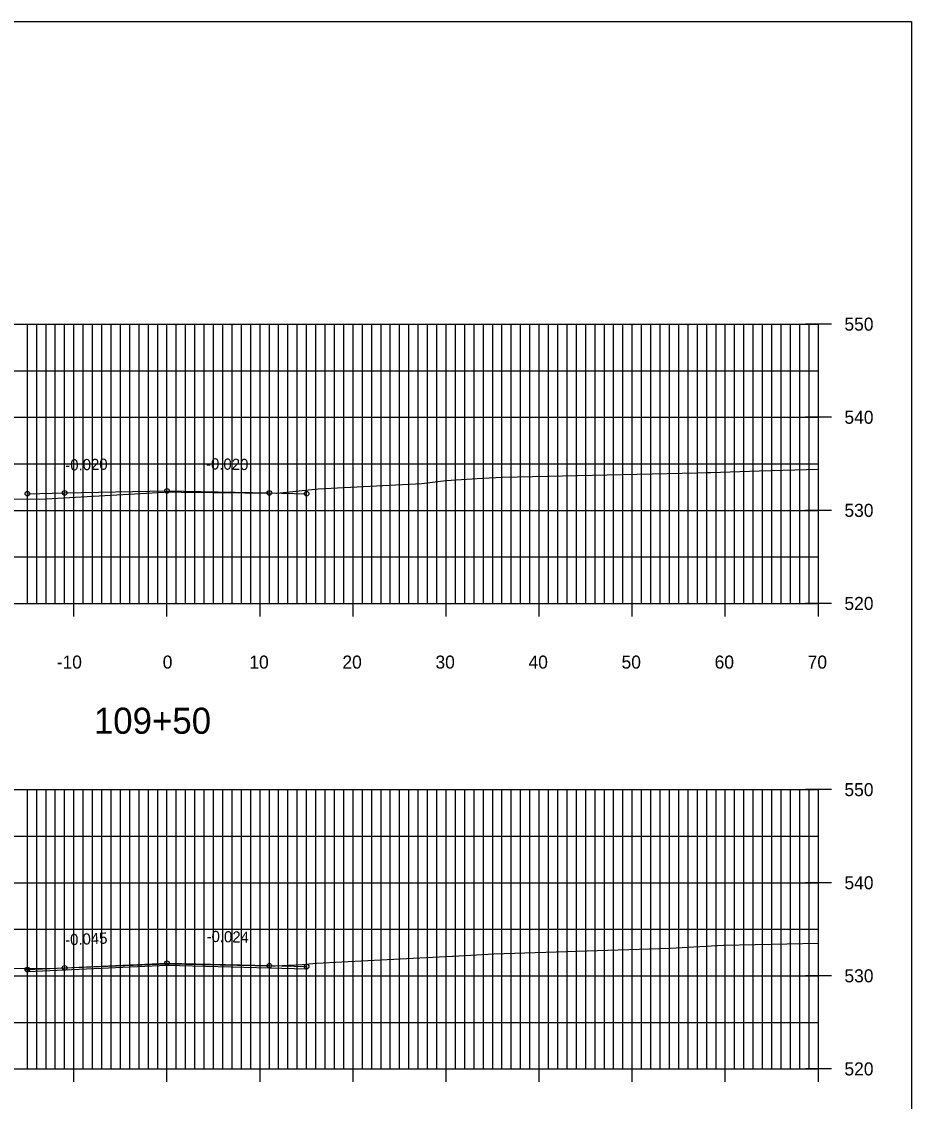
# Model space of a CAD drawing. Extents: x 1509063 to 1512863, y 401160 to 402918.
# Drawn here: x 1512407.1 to 1512502.7, y 402346.1 to 402462.1 of the extents above; entities that cross this region are included whole.
import ezdxf

# ---------------------------------------------------------------- set-up
doc = ezdxf.new("R2010")
doc.units = 0
for name, color, linetype in [('NBL1', 7, 'Continuous'), ('PET_P', 7, 'Continuous'), ('PRC', 7, 'Continuous'), ('PSP_P', 7, 'Continuous'), ('RBS_P', 7, 'Continuous'), ('XAX_P', 7, 'Continuous'), ('XAXTIC_P', 7, 'Continuous'), ('XAXTXT_P_T', 7, 'Continuous'), ('XGL_P', 7, 'Continuous'), ('XSL1_P', 7, 'Continuous'), ('XSL1_P_T', 7, 'Continuous'), ('XSL3_P', 7, 'Continuous'), ('XSLOG', 7, 'Continuous')]:
    doc.layers.add(name, color=color, linetype=linetype)

msp = doc.modelspace()

# ---------------------------------------------------------------- linework, layer by layer
at = {"layer": 'NBL1'}
msp.add_lwpolyline([(1512502.73, 402252.08), (1512182.73, 402252.08), (1512182.73, 402462.08), (1512502.73, 402462.08)], close=True, dxfattribs=at)
at = {"layer": 'PET_P'}
for centre in [(1512411.73, 402411.45), (1512433.73, 402411.45), (1512433.73, 402360.67), (1512411.73, 402360.43)]:
    msp.add_circle(centre, 0.25, dxfattribs=at)
at = {"layer": 'PRC'}
for centre in [(1512422.73, 402411.67), (1512422.73, 402360.93)]:
    msp.add_circle(centre, 0.25, dxfattribs=at)
at = {"layer": 'PSP_P'}
for centre in [(1512407.73, 402411.37), (1512437.73, 402411.37), (1512407.73, 402360.25), (1512437.73, 402360.57)]:
    msp.add_circle(centre, 0.25, dxfattribs=at)
at = {"layer": 'RBS_P'}
msp.add_lwpolyline([(1512407.73, 402360.25), (1512407.73, 402360.5), (1512407.73, 402360.25), (1512407.48, 402360.25), (1512407.73, 402360.25), (1512407.73, 402360), (1512407.73, 402360.25), (1512407.98, 402360.25)], dxfattribs=at)
at = {"layer": 'XAX_P'}
for p, q in [((1512422.73, 402399.58), (1512422.73, 402429.58)), ((1512492.73, 402399.58), (1512492.73, 402429.58)), ((1512352.73, 402399.58), (1512492.73, 402399.58)), ((1512422.73, 402349.58), (1512422.73, 402379.58)), ((1512492.73, 402349.58), (1512492.73, 402379.58)), ((1512352.73, 402349.58), (1512492.73, 402349.58))]:
    msp.add_line(p, q, dxfattribs=at)
at = {"layer": 'XAXTIC_P'}
for p, q in [((1512421.33, 402429.58), (1512424.13, 402429.58)), ((1512494.13, 402429.58), (1512491.33, 402429.58)), ((1512421.33, 402419.58), (1512424.13, 402419.58)), ((1512494.13, 402419.58), (1512491.33, 402419.58)), ((1512421.33, 402409.58), (1512424.13, 402409.58)), ((1512494.13, 402409.58), (1512491.33, 402409.58)), ((1512412.73, 402398.18), (1512412.73, 402400.98)), ((1512422.73, 402398.18), (1512422.73, 402400.98)), ((1512432.73, 402398.18), (1512432.73, 402400.98)), ((1512442.73, 402398.18), (1512442.73, 402400.98)), ((1512452.73, 402398.18), (1512452.73, 402400.98)), ((1512462.73, 402398.18), (1512462.73, 402400.98)), ((1512472.73, 402398.18), (1512472.73, 402400.98)), ((1512482.73, 402398.18), (1512482.73, 402400.98)), ((1512492.73, 402398.18), (1512492.73, 402400.98)), ((1512421.33, 402399.58), (1512424.13, 402399.58)), ((1512494.13, 402399.58), (1512491.33, 402399.58)), ((1512421.33, 402379.58), (1512424.13, 402379.58)), ((1512494.13, 402379.58), (1512491.33, 402379.58)), ((1512421.33, 402369.58), (1512424.13, 402369.58)), ((1512494.13, 402369.58), (1512491.33, 402369.58)), ((1512421.33, 402359.58), (1512424.13, 402359.58)), ((1512494.13, 402359.58), (1512491.33, 402359.58)), ((1512412.73, 402348.18), (1512412.73, 402350.98)), ((1512422.73, 402348.18), (1512422.73, 402350.98)), ((1512432.73, 402348.18), (1512432.73, 402350.98)), ((1512442.73, 402348.18), (1512442.73, 402350.98)), ((1512452.73, 402348.18), (1512452.73, 402350.98)), ((1512462.73, 402348.18), (1512462.73, 402350.98)), ((1512472.73, 402348.18), (1512472.73, 402350.98)), ((1512482.73, 402348.18), (1512482.73, 402350.98)), ((1512492.73, 402348.18), (1512492.73, 402350.98)), ((1512421.33, 402349.58), (1512424.13, 402349.58)), ((1512494.13, 402349.58), (1512491.33, 402349.58))]:
    msp.add_line(p, q, dxfattribs=at)
at = {"layer": 'XGL_P'}
for p, q in [((1512352.73, 402429.58), (1512492.73, 402429.58)), ((1512407.73, 402399.58), (1512407.73, 402429.58)), ((1512408.73, 402399.58), (1512408.73, 402429.58)), ((1512409.73, 402399.58), (1512409.73, 402429.58)), ((1512410.73, 402399.58), (1512410.73, 402429.58)), ((1512411.73, 402399.58), (1512411.73, 402429.58)), ((1512412.73, 402399.58), (1512412.73, 402429.58)), ((1512413.73, 402399.58), (1512413.73, 402429.58)), ((1512414.73, 402399.58), (1512414.73, 402429.58)), ((1512415.73, 402399.58), (1512415.73, 402429.58)), ((1512416.73, 402399.58), (1512416.73, 402429.58)), ((1512417.73, 402399.58), (1512417.73, 402429.58)), ((1512418.73, 402399.58), (1512418.73, 402429.58)), ((1512419.73, 402399.58), (1512419.73, 402429.58)), ((1512420.73, 402399.58), (1512420.73, 402429.58)), ((1512421.73, 402399.58), (1512421.73, 402429.58)), ((1512422.73, 402399.58), (1512422.73, 402429.58)), ((1512423.73, 402399.58), (1512423.73, 402429.58)), ((1512424.73, 402399.58), (1512424.73, 402429.58)), ((1512425.73, 402399.58), (1512425.73, 402429.58)), ((1512426.73, 402399.58), (1512426.73, 402429.58)), ((1512427.73, 402399.58), (1512427.73, 402429.58)), ((1512428.73, 402399.58), (1512428.73, 402429.58)), ((1512429.73, 402399.58), (1512429.73, 402429.58)), ((1512430.73, 402399.58), (1512430.73, 402429.58)), ((1512431.73, 402399.58), (1512431.73, 402429.58)), ((1512432.73, 402399.58), (1512432.73, 402429.58)), ((1512433.73, 402399.58), (1512433.73, 402429.58)), ((1512434.73, 402399.58), (1512434.73, 402429.58)), ((1512435.73, 402399.58), (1512435.73, 402429.58)), ((1512436.73, 402399.58), (1512436.73, 402429.58)), ((1512437.73, 402399.58), (1512437.73, 402429.58)), ((1512438.73, 402399.58), (1512438.73, 402429.58)), ((1512439.73, 402399.58), (1512439.73, 402429.58)), ((1512440.73, 402399.58), (1512440.73, 402429.58)), ((1512441.73, 402399.58), (1512441.73, 402429.58)), ((1512442.73, 402399.58), (1512442.73, 402429.58)), ((1512443.73, 402399.58), (1512443.73, 402429.58)), ((1512444.73, 402399.58), (1512444.73, 402429.58)), ((1512445.73, 402399.58), (1512445.73, 402429.58)), ((1512446.73, 402399.58), (1512446.73, 402429.58)), ((1512447.73, 402399.58), (1512447.73, 402429.58)), ((1512448.73, 402399.58), (1512448.73, 402429.58)), ((1512449.73, 402399.58), (1512449.73, 402429.58)), ((1512450.73, 402399.58), (1512450.73, 402429.58)), ((1512451.73, 402399.58), (1512451.73, 402429.58)), ((1512452.73, 402399.58), (1512452.73, 402429.58)), ((1512453.73, 402399.58), (1512453.73, 402429.58)), ((1512454.73, 402399.58), (1512454.73, 402429.58)), ((1512455.73, 402399.58), (1512455.73, 402429.58)), ((1512456.73, 402399.58), (1512456.73, 402429.58)), ((1512457.73, 402399.58), (1512457.73, 402429.58)), ((1512458.73, 402399.58), (1512458.73, 402429.58)), ((1512459.73, 402399.58), (1512459.73, 402429.58)), ((1512460.73, 402399.58), (1512460.73, 402429.58)), ((1512461.73, 402399.58), (1512461.73, 402429.58)), ((1512462.73, 402399.58), (1512462.73, 402429.58)), ((1512463.73, 402399.58), (1512463.73, 402429.58)), ((1512464.73, 402399.58), (1512464.73, 402429.58)), ((1512465.73, 402399.58), (1512465.73, 402429.58)), ((1512466.73, 402399.58), (1512466.73, 402429.58)), ((1512467.73, 402399.58), (1512467.73, 402429.58)), ((1512468.73, 402399.58), (1512468.73, 402429.58)), ((1512469.73, 402399.58), (1512469.73, 402429.58)), ((1512470.73, 402399.58), (1512470.73, 402429.58)), ((1512471.73, 402399.58), (1512471.73, 402429.58)), ((1512472.73, 402399.58), (1512472.73, 402429.58)), ((1512473.73, 402399.58), (1512473.73, 402429.58)), ((1512474.73, 402399.58), (1512474.73, 402429.58)), ((1512475.73, 402399.58), (1512475.73, 402429.58)), ((1512476.73, 402399.58), (1512476.73, 402429.58)), ((1512477.73, 402399.58), (1512477.73, 402429.58)), ((1512478.73, 402399.58), (1512478.73, 402429.58)), ((1512479.73, 402399.58), (1512479.73, 402429.58)), ((1512480.73, 402399.58), (1512480.73, 402429.58)), ((1512481.73, 402399.58), (1512481.73, 402429.58)), ((1512482.73, 402399.58), (1512482.73, 402429.58)), ((1512483.73, 402399.58), (1512483.73, 402429.58)), ((1512484.73, 402399.58), (1512484.73, 402429.58)), ((1512485.73, 402399.58), (1512485.73, 402429.58)), ((1512486.73, 402399.58), (1512486.73, 402429.58)), ((1512487.73, 402399.58), (1512487.73, 402429.58)), ((1512488.73, 402399.58), (1512488.73, 402429.58)), ((1512489.73, 402399.58), (1512489.73, 402429.58)), ((1512490.73, 402399.58), (1512490.73, 402429.58)), ((1512491.73, 402399.58), (1512491.73, 402429.58)), ((1512492.73, 402399.58), (1512492.73, 402429.58)), ((1512352.73, 402424.58), (1512492.73, 402424.58)), ((1512352.73, 402419.58), (1512492.73, 402419.58)), ((1512352.73, 402414.58), (1512492.73, 402414.58)), ((1512352.73, 402409.58), (1512492.73, 402409.58)), ((1512352.73, 402404.58), (1512492.73, 402404.58)), ((1512352.73, 402399.58), (1512492.73, 402399.58)), ((1512352.73, 402379.58), (1512492.73, 402379.58)), ((1512407.73, 402349.58), (1512407.73, 402379.58)), ((1512408.73, 402349.58), (1512408.73, 402379.58)), ((1512409.73, 402349.58), (1512409.73, 402379.58)), ((1512410.73, 402349.58), (1512410.73, 402379.58)), ((1512411.73, 402349.58), (1512411.73, 402379.58)), ((1512412.73, 402349.58), (1512412.73, 402379.58)), ((1512413.73, 402349.58), (1512413.73, 402379.58)), ((1512414.73, 402349.58), (1512414.73, 402379.58)), ((1512415.73, 402349.58), (1512415.73, 402379.58)), ((1512416.73, 402349.58), (1512416.73, 402379.58)), ((1512417.73, 402349.58), (1512417.73, 402379.58)), ((1512418.73, 402349.58), (1512418.73, 402379.58)), ((1512419.73, 402349.58), (1512419.73, 402379.58)), ((1512420.73, 402349.58), (1512420.73, 402379.58)), ((1512421.73, 402349.58), (1512421.73, 402379.58)), ((1512422.73, 402349.58), (1512422.73, 402379.58)), ((1512423.73, 402349.58), (1512423.73, 402379.58)), ((1512424.73, 402349.58), (1512424.73, 402379.58)), ((1512425.73, 402349.58), (1512425.73, 402379.58)), ((1512426.73, 402349.58), (1512426.73, 402379.58)), ((1512427.73, 402349.58), (1512427.73, 402379.58)), ((1512428.73, 402349.58), (1512428.73, 402379.58)), ((1512429.73, 402349.58), (1512429.73, 402379.58)), ((1512430.73, 402349.58), (1512430.73, 402379.58)), ((1512431.73, 402349.58), (1512431.73, 402379.58)), ((1512432.73, 402349.58), (1512432.73, 402379.58)), ((1512433.73, 402349.58), (1512433.73, 402379.58)), ((1512434.73, 402349.58), (1512434.73, 402379.58)), ((1512435.73, 402349.58), (1512435.73, 402379.58)), ((1512436.73, 402349.58), (1512436.73, 402379.58)), ((1512437.73, 402349.58), (1512437.73, 402379.58)), ((1512438.73, 402349.58), (1512438.73, 402379.58)), ((1512439.73, 402349.58), (1512439.73, 402379.58)), ((1512440.73, 402349.58), (1512440.73, 402379.58)), ((1512441.73, 402349.58), (1512441.73, 402379.58)), ((1512442.73, 402349.58), (1512442.73, 402379.58)), ((1512443.73, 402349.58), (1512443.73, 402379.58)), ((1512444.73, 402349.58), (1512444.73, 402379.58)), ((1512445.73, 402349.58), (1512445.73, 402379.58)), ((1512446.73, 402349.58), (1512446.73, 402379.58)), ((1512447.73, 402349.58), (1512447.73, 402379.58)), ((1512448.73, 402349.58), (1512448.73, 402379.58)), ((1512449.73, 402349.58), (1512449.73, 402379.58)), ((1512450.73, 402349.58), (1512450.73, 402379.58)), ((1512451.73, 402349.58), (1512451.73, 402379.58)), ((1512452.73, 402349.58), (1512452.73, 402379.58)), ((1512453.73, 402349.58), (1512453.73, 402379.58)), ((1512454.73, 402349.58), (1512454.73, 402379.58)), ((1512455.73, 402349.58), (1512455.73, 402379.58)), ((1512456.73, 402349.58), (1512456.73, 402379.58)), ((1512457.73, 402349.58), (1512457.73, 402379.58)), ((1512458.73, 402349.58), (1512458.73, 402379.58)), ((1512459.73, 402349.58), (1512459.73, 402379.58)), ((1512460.73, 402349.58), (1512460.73, 402379.58)), ((1512461.73, 402349.58), (1512461.73, 402379.58)), ((1512462.73, 402349.58), (1512462.73, 402379.58)), ((1512463.73, 402349.58), (1512463.73, 402379.58)), ((1512464.73, 402349.58), (1512464.73, 402379.58)), ((1512465.73, 402349.58), (1512465.73, 402379.58)), ((1512466.73, 402349.58), (1512466.73, 402379.58)), ((1512467.73, 402349.58), (1512467.73, 402379.58)), ((1512468.73, 402349.58), (1512468.73, 402379.58)), ((1512469.73, 402349.58), (1512469.73, 402379.58)), ((1512470.73, 402349.58), (1512470.73, 402379.58)), ((1512471.73, 402349.58), (1512471.73, 402379.58)), ((1512472.73, 402349.58), (1512472.73, 402379.58)), ((1512473.73, 402349.58), (1512473.73, 402379.58)), ((1512474.73, 402349.58), (1512474.73, 402379.58)), ((1512475.73, 402349.58), (1512475.73, 402379.58)), ((1512476.73, 402349.58), (1512476.73, 402379.58)), ((1512477.73, 402349.58), (1512477.73, 402379.58)), ((1512478.73, 402349.58), (1512478.73, 402379.58)), ((1512479.73, 402349.58), (1512479.73, 402379.58)), ((1512480.73, 402349.58), (1512480.73, 402379.58)), ((1512481.73, 402349.58), (1512481.73, 402379.58)), ((1512482.73, 402349.58), (1512482.73, 402379.58)), ((1512483.73, 402349.58), (1512483.73, 402379.58)), ((1512484.73, 402349.58), (1512484.73, 402379.58)), ((1512485.73, 402349.58), (1512485.73, 402379.58)), ((1512486.73, 402349.58), (1512486.73, 402379.58)), ((1512487.73, 402349.58), (1512487.73, 402379.58)), ((1512488.73, 402349.58), (1512488.73, 402379.58)), ((1512489.73, 402349.58), (1512489.73, 402379.58)), ((1512490.73, 402349.58), (1512490.73, 402379.58)), ((1512491.73, 402349.58), (1512491.73, 402379.58)), ((1512492.73, 402349.58), (1512492.73, 402379.58)), ((1512352.73, 402374.58), (1512492.73, 402374.58)), ((1512352.73, 402369.58), (1512492.73, 402369.58)), ((1512352.73, 402364.58), (1512492.73, 402364.58)), ((1512352.73, 402359.58), (1512492.73, 402359.58)), ((1512352.73, 402354.58), (1512492.73, 402354.58)), ((1512352.73, 402349.58), (1512492.73, 402349.58))]:
    msp.add_line(p, q, dxfattribs=at)
at = {"layer": 'XSL1_P'}
for points in [[(1512407.73, 402411.37), (1512411.73, 402411.45), (1512422.73, 402411.67), (1512433.73, 402411.45), (1512437.73, 402411.37)], [(1512407.73, 402360.25), (1512411.73, 402360.43), (1512422.73, 402360.93), (1512433.73, 402360.67), (1512437.73, 402360.57)]]:
    msp.add_lwpolyline(points, dxfattribs=at)
at = {"layer": 'XSL3_P'}
msp.add_lwpolyline([(1512411.73, 402360.18), (1512407.77, 402360), (1512407.73, 402360.26), (1512411.73, 402360.44), (1512422.72, 402360.93), (1512433.73, 402360.67), (1512437.73, 402360.57), (1512437.73, 402360.31), (1512433.73, 402360.41), (1512422.72, 402360.67)], close=True, dxfattribs=at)
at = {"layer": 'XSLOG'}
for points in [[(1512405.89, 402410.81), (1512409.07, 402410.78), (1512422.42, 402411.52), (1512422.81, 402411.55), (1512424.28, 402411.53), (1512434.5, 402411.43), (1512434.55, 402411.44), (1512438.99, 402411.9), (1512450.1, 402412.48), (1512452.71, 402412.79), (1512456.62, 402413.02), (1512458.79, 402413.16), (1512479.69, 402413.6), (1512480.73, 402413.63), (1512481.16, 402413.65), (1512486.35, 402413.82), (1512492.73, 402414.02)], [(1512352.73, 402360.97), (1512360.04, 402360.95), (1512372.97, 402360.5), (1512391.76, 402360.36), (1512398.22, 402360.38), (1512398.8, 402360.48), (1512404.99, 402360.41), (1512409.91, 402360.35), (1512409.98, 402360.35), (1512422.76, 402360.86), (1512434.12, 402360.66), (1512434.34, 402360.65), (1512437.3, 402360.81), (1512437.99, 402360.85), (1512438.82, 402360.95), (1512441.51, 402361.07), (1512453.39, 402361.7), (1512453.48, 402361.69), (1512457.86, 402361.94), (1512476.8, 402362.56), (1512482.52, 402362.86), (1512492.73, 402363.09)]]:
    msp.add_lwpolyline(points, dxfattribs=at)

# ---------------------------------------------------------------- texts
at = {"layer": 'XAXTXT_P_T'}
for s, height, p in [('550', 1.4, (1512495.53, 402428.88)), ('540', 1.4, (1512495.53, 402418.88)), ('530', 1.4, (1512495.53, 402408.88)), ('520', 1.4, (1512495.53, 402398.88)), ('-10', 1.4, (1512410.88, 402392.58)), ('0', 1.4, (1512422.27, 402392.58)), ('10', 1.4, (1512431.58, 402392.58)), ('20', 1.4, (1512441.58, 402392.58)), ('30', 1.4, (1512451.58, 402392.58)), ('40', 1.4, (1512461.58, 402392.58)), ('50', 1.4, (1512471.58, 402392.58)), ('60', 1.4, (1512481.58, 402392.58)), ('70', 1.4, (1512491.58, 402392.58)), ('109+50', 2.8, (1512414.87, 402385.58)), ('550', 1.4, (1512495.53, 402378.88)), ('540', 1.4, (1512495.53, 402368.88)), ('530', 1.4, (1512495.53, 402358.88)), ('520', 1.4, (1512495.53, 402348.88))]:
    msp.add_text(s, height=height, dxfattribs=at).set_placement(p)
at = {"layer": 'XSL1_P_T'}
for s, rotation, p in [('-0.020', 1.1458, (1512411.81, 402413.85)), ('-0.020', 358.8542, (1512426.91, 402413.99)), ('-0.024', 358.6194, (1512426.97, 402363.23)), ('-0.045', 2.5899, (1512411.81, 402362.84))]:
    msp.add_text(s, height=1.2, rotation=rotation, dxfattribs=at).set_placement(p)

doc.saveas('drawing.dxf')
